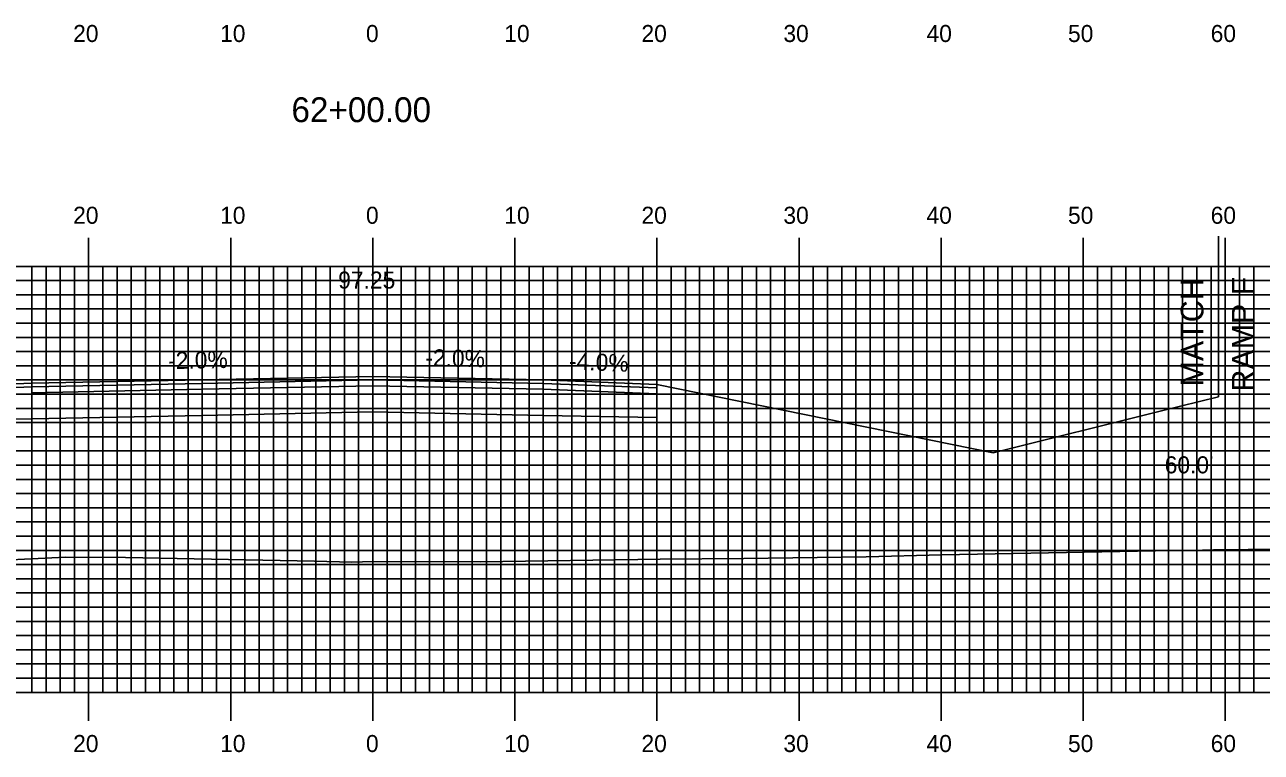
# Model space of a CAD drawing. Extents: x 1757856 to 1758199, y 442591 to 442811.
# Drawn here: x 1757997.1 to 1758084.2, y 442704.4 to 442755.7 of the extents above; entities that cross this region are included whole.
import ezdxf

# ---------------------------------------------------------------- set-up
doc = ezdxf.new("R2010")
doc.units = 0
for name, color, linetype in [('ANNOTATION', 7, 'Continuous'), ('D_Roadway_Centerline', 7, 'Continuous'), ('D_Roadway_Centerline_Text', 7, 'Continuous'), ('D_Roadway_Edge_Shoulder', 7, 'Continuous'), ('D_Roadway_Edge_TW', 7, 'Continuous'), ('D_Roadway_Pavement', 7, 'Continuous'), ('D_Roadway_SlopeLines', 7, 'Continuous'), ('D_Roadway_SubGrade', 7, 'Continuous'), ('D_Text_Standard', 7, 'Continuous'), ('H_V ANNOTATION', 7, 'Continuous'), ('MAJOR', 7, 'Continuous'), ('MINOR', 7, 'Continuous'), ('S_Roadway_Centerline', 7, 'Continuous')]:
    doc.layers.add(name, color=color, linetype=linetype)

msp = doc.modelspace()

# ---------------------------------------------------------------- linework, layer by layer
at = {"layer": 'D_Roadway_Centerline'}
msp.add_lwpolyline([(1758081.125, 442729.483), (1758081.127, 442729.483), (1758081.136, 442729.485)], dxfattribs=at)
at = {"layer": 'D_Roadway_Edge_Shoulder'}
for points in [[(1757997.622, 442730.436), (1757989.622, 442730.116), (1757989.622, 442729.866), (1757997.622, 442730.186)], [(1758033.622, 442730.676), (1758041.622, 442730.356), (1758041.622, 442730.106), (1758033.622, 442730.426)]]:
    msp.add_lwpolyline(points, close=True, dxfattribs=at)
at = {"layer": 'D_Roadway_Edge_TW'}
for points in [[(1758009.622, 442730.426), (1758009.622, 442730.676), (1758021.622, 442730.916), (1758033.622, 442730.676), (1758033.622, 442730.426), (1758021.622, 442730.666)], [(1758009.622, 442730.676), (1757997.622, 442730.436), (1757997.622, 442730.186), (1758009.622, 442730.426)]]:
    msp.add_lwpolyline(points, close=True, dxfattribs=at)
msp.add_lwpolyline([(1758009.622, 442730.676), (1758009.622, 442730.426)], dxfattribs=at)
at = {"layer": 'D_Roadway_Pavement'}
for points in [[(1758009.622, 442730.426), (1757997.622, 442730.186), (1757997.622, 442729.769), (1758009.622, 442730.009)], [(1758009.622, 442730.009), (1758009.622, 442730.426), (1758021.622, 442730.666), (1758033.622, 442730.426), (1758033.622, 442730.009), (1758021.622, 442730.249)], [(1758033.622, 442730.426), (1758041.622, 442730.106), (1758041.622, 442729.689), (1758033.622, 442730.009)]]:
    msp.add_lwpolyline(points, close=True, dxfattribs=at)
for points in [[(1757997.622, 442730.186), (1757997.622, 442729.769)], [(1758009.622, 442730.426), (1758009.622, 442730.009)], [(1758009.622, 442730.426), (1758009.622, 442730.009)]]:
    msp.add_lwpolyline(points, dxfattribs=at)
at = {"layer": 'D_Roadway_SlopeLines'}
msp.add_lwpolyline([(1758041.622, 442730.356), (1758065.295, 442725.525)], dxfattribs=at)
at = {"layer": 'D_Roadway_SubGrade'}
for p, q in [((1758081.136, 442740.782), (1758081.136, 442729.485)), ((1758081.136, 442729.485), (1758081.136, 442732.055)), ((1758081.136, 442729.485), (1758077.136, 442728.485)), ((1758077.136, 442728.485), (1758065.295, 442725.525))]:
    msp.add_line(p, q, dxfattribs=at)
for points in [[(1757997.622, 442729.769), (1757997.622, 442730.186), (1757989.622, 442729.866), (1757989.622, 442730.116), (1757979.448, 442727.572), (1757997.622, 442727.936)], [(1758009.622, 442730.009), (1757997.622, 442729.769), (1757997.622, 442727.936), (1758009.622, 442728.176)], [(1758009.622, 442728.176), (1758009.622, 442730.009), (1758021.622, 442730.249), (1758033.622, 442730.009), (1758033.622, 442728.176), (1758021.622, 442728.416)], [(1758033.622, 442730.009), (1758041.622, 442729.689), (1758041.622, 442730.106), (1758041.622, 442730.356), (1758041.622, 442728.016), (1758033.622, 442728.176)]]:
    msp.add_lwpolyline(points, close=True, dxfattribs=at)
msp.add_lwpolyline([(1758009.622, 442730.009), (1758009.622, 442728.176)], dxfattribs=at)
at = {"layer": 'MAJOR'}
for p, q in [((1758001.622, 442740.669), (1758001.622, 442738.665)), ((1758011.622, 442740.669), (1758011.622, 442738.665)), ((1758021.622, 442740.669), (1758021.622, 442738.665)), ((1758031.622, 442740.669), (1758031.622, 442738.665)), ((1758041.622, 442740.669), (1758041.622, 442738.665)), ((1758051.622, 442740.669), (1758051.622, 442738.665)), ((1758061.622, 442740.669), (1758061.622, 442738.665)), ((1758071.622, 442740.669), (1758071.622, 442738.665)), ((1758081.622, 442740.669), (1758081.622, 442738.665)), ((1757881.622, 442738.665), (1758161.622, 442738.665)), ((1757881.622, 442738.665), (1758161.622, 442738.665)), ((1758001.622, 442708.665), (1758001.622, 442738.665)), ((1758011.622, 442708.665), (1758011.622, 442738.665)), ((1758021.622, 442708.665), (1758021.622, 442738.665)), ((1758031.622, 442708.665), (1758031.622, 442738.665)), ((1758041.622, 442708.665), (1758041.622, 442738.665)), ((1758051.622, 442708.665), (1758051.622, 442738.665)), ((1758061.622, 442708.665), (1758061.622, 442738.665)), ((1758071.622, 442708.665), (1758071.622, 442738.665)), ((1758081.622, 442708.665), (1758081.622, 442738.665)), ((1757881.622, 442733.665), (1758161.622, 442733.665)), ((1757881.622, 442728.665), (1758161.622, 442728.665)), ((1757881.622, 442723.665), (1758161.622, 442723.665)), ((1757881.622, 442718.665), (1758161.622, 442718.665)), ((1757881.622, 442713.665), (1758161.622, 442713.665)), ((1757881.622, 442708.665), (1758161.622, 442708.665)), ((1757881.622, 442708.665), (1758161.622, 442708.665)), ((1758001.622, 442706.661), (1758001.622, 442708.665)), ((1758011.622, 442706.661), (1758011.622, 442708.665)), ((1758021.622, 442706.661), (1758021.622, 442708.665)), ((1758031.622, 442706.661), (1758031.622, 442708.665)), ((1758041.622, 442706.661), (1758041.622, 442708.665)), ((1758051.622, 442706.661), (1758051.622, 442708.665)), ((1758061.622, 442706.661), (1758061.622, 442708.665)), ((1758071.622, 442706.661), (1758071.622, 442708.665)), ((1758081.622, 442706.661), (1758081.622, 442708.665))]:
    msp.add_line(p, q, dxfattribs=at)
at = {"layer": 'MINOR'}
for p, q in [((1757997.622, 442708.665), (1757997.622, 442738.665)), ((1757998.622, 442708.665), (1757998.622, 442738.665)), ((1757999.622, 442708.665), (1757999.622, 442738.665)), ((1758000.622, 442708.665), (1758000.622, 442738.665)), ((1758002.622, 442708.665), (1758002.622, 442738.665)), ((1758003.622, 442708.665), (1758003.622, 442738.665)), ((1758004.622, 442708.665), (1758004.622, 442738.665)), ((1758005.622, 442708.665), (1758005.622, 442738.665)), ((1758006.622, 442708.665), (1758006.622, 442738.665)), ((1758007.622, 442708.665), (1758007.622, 442738.665)), ((1758008.622, 442708.665), (1758008.622, 442738.665)), ((1758009.622, 442708.665), (1758009.622, 442738.665)), ((1758010.622, 442708.665), (1758010.622, 442738.665)), ((1758012.622, 442708.665), (1758012.622, 442738.665)), ((1758013.622, 442708.665), (1758013.622, 442738.665)), ((1758014.622, 442708.665), (1758014.622, 442738.665)), ((1758015.622, 442708.665), (1758015.622, 442738.665)), ((1758016.622, 442708.665), (1758016.622, 442738.665)), ((1758017.622, 442708.665), (1758017.622, 442738.665)), ((1758018.622, 442708.665), (1758018.622, 442738.665)), ((1758019.622, 442708.665), (1758019.622, 442738.665)), ((1758020.622, 442708.665), (1758020.622, 442738.665)), ((1758022.622, 442708.665), (1758022.622, 442738.665)), ((1758023.622, 442708.665), (1758023.622, 442738.665)), ((1758024.622, 442708.665), (1758024.622, 442738.665)), ((1758025.622, 442708.665), (1758025.622, 442738.665)), ((1758026.622, 442708.665), (1758026.622, 442738.665)), ((1758027.622, 442708.665), (1758027.622, 442738.665)), ((1758028.622, 442708.665), (1758028.622, 442738.665)), ((1758029.622, 442708.665), (1758029.622, 442738.665)), ((1758030.622, 442708.665), (1758030.622, 442738.665)), ((1758032.622, 442708.665), (1758032.622, 442738.665)), ((1758033.622, 442708.665), (1758033.622, 442738.665)), ((1758034.622, 442708.665), (1758034.622, 442738.665)), ((1758035.622, 442708.665), (1758035.622, 442738.665)), ((1758036.622, 442708.665), (1758036.622, 442738.665)), ((1758037.622, 442708.665), (1758037.622, 442738.665)), ((1758038.622, 442708.665), (1758038.622, 442738.665)), ((1758039.622, 442708.665), (1758039.622, 442738.665)), ((1758040.622, 442708.665), (1758040.622, 442738.665)), ((1758042.622, 442708.665), (1758042.622, 442738.665)), ((1758043.622, 442708.665), (1758043.622, 442738.665)), ((1758044.622, 442708.665), (1758044.622, 442738.665)), ((1758045.622, 442708.665), (1758045.622, 442738.665)), ((1758046.622, 442708.665), (1758046.622, 442738.665)), ((1758047.622, 442708.665), (1758047.622, 442738.665)), ((1758048.622, 442708.665), (1758048.622, 442738.665)), ((1758049.622, 442708.665), (1758049.622, 442738.665)), ((1758050.622, 442708.665), (1758050.622, 442738.665)), ((1758052.622, 442708.665), (1758052.622, 442738.665)), ((1758053.622, 442708.665), (1758053.622, 442738.665)), ((1758054.622, 442708.665), (1758054.622, 442738.665)), ((1758055.622, 442708.665), (1758055.622, 442738.665)), ((1758056.622, 442708.665), (1758056.622, 442738.665)), ((1758057.622, 442708.665), (1758057.622, 442738.665)), ((1758058.622, 442708.665), (1758058.622, 442738.665)), ((1758059.622, 442708.665), (1758059.622, 442738.665)), ((1758060.622, 442708.665), (1758060.622, 442738.665)), ((1758062.622, 442708.665), (1758062.622, 442738.665)), ((1758063.622, 442708.665), (1758063.622, 442738.665)), ((1758064.622, 442708.665), (1758064.622, 442738.665)), ((1758065.622, 442708.665), (1758065.622, 442738.665)), ((1758066.622, 442708.665), (1758066.622, 442738.665)), ((1758067.622, 442708.665), (1758067.622, 442738.665)), ((1758068.622, 442708.665), (1758068.622, 442738.665)), ((1758069.622, 442708.665), (1758069.622, 442738.665)), ((1758070.622, 442708.665), (1758070.622, 442738.665)), ((1758072.622, 442708.665), (1758072.622, 442738.665)), ((1758073.622, 442708.665), (1758073.622, 442738.665)), ((1758074.622, 442708.665), (1758074.622, 442738.665)), ((1758075.622, 442708.665), (1758075.622, 442738.665)), ((1758076.622, 442708.665), (1758076.622, 442738.665)), ((1758077.622, 442708.665), (1758077.622, 442738.665)), ((1758078.622, 442708.665), (1758078.622, 442738.665)), ((1758079.622, 442708.665), (1758079.622, 442738.665)), ((1758080.622, 442708.665), (1758080.622, 442738.665)), ((1758082.622, 442708.665), (1758082.622, 442738.665)), ((1758083.622, 442708.665), (1758083.622, 442738.665)), ((1757881.622, 442737.665), (1758161.622, 442737.665)), ((1757881.622, 442736.665), (1758161.622, 442736.665)), ((1757881.622, 442735.665), (1758161.622, 442735.665)), ((1757881.622, 442734.665), (1758161.622, 442734.665)), ((1757881.622, 442732.665), (1758161.622, 442732.665)), ((1757881.622, 442731.665), (1758161.622, 442731.665)), ((1757881.622, 442730.665), (1758161.622, 442730.665)), ((1757881.622, 442729.665), (1758161.622, 442729.665)), ((1757881.622, 442727.665), (1758161.622, 442727.665)), ((1757881.622, 442726.665), (1758161.622, 442726.665)), ((1757881.622, 442725.665), (1758161.622, 442725.665)), ((1757881.622, 442724.665), (1758161.622, 442724.665)), ((1757881.622, 442722.665), (1758161.622, 442722.665)), ((1757881.622, 442721.665), (1758161.622, 442721.665)), ((1757881.622, 442720.665), (1758161.622, 442720.665)), ((1757881.622, 442719.665), (1758161.622, 442719.665)), ((1757881.622, 442717.665), (1758161.622, 442717.665)), ((1757881.622, 442716.665), (1758161.622, 442716.665)), ((1757881.622, 442715.665), (1758161.622, 442715.665)), ((1757881.622, 442714.665), (1758161.622, 442714.665)), ((1757881.622, 442712.665), (1758161.622, 442712.665)), ((1757881.622, 442711.665), (1758161.622, 442711.665)), ((1757881.622, 442710.665), (1758161.622, 442710.665)), ((1757881.622, 442709.665), (1758161.622, 442709.665))]:
    msp.add_line(p, q, dxfattribs=at)
at = {"layer": 'S_Roadway_Centerline'}
msp.add_lwpolyline([(1757938.966, 442717.046), (1757947.497, 442716.919), (1757951.509, 442717.005), (1757965.228, 442717.399), (1757972.726, 442717.596), (1757984.329, 442717.521), (1757986.504, 442717.521), (1757999.995, 442718.195), (1758004.218, 442718.161), (1758017.529, 442717.914), (1758020.15, 442717.828), (1758021.643, 442717.878), (1758029.205, 442717.867), (1758041.848, 442718.043), (1758047.726, 442718.088), (1758056.337, 442718.223), (1758061.682, 442718.344), (1758077.96, 442718.661), (1758080.017, 442718.691), (1758080.792, 442718.702), (1758100.242, 442718.897)], dxfattribs=at)

# ---------------------------------------------------------------- texts
at = {"layer": 'ANNOTATION'}
for s, height, rotation, p in [('RAMP F', 1.6, 90, (1758083.689, 442729.853)), ('MATCH', 1.6, 90, (1758080.089, 442730.214)), ('-2.0%', 1.2, 1.14576, (1758007.228, 442731.428)), ('-2.0%', 1.2, 358.85424, (1758025.308, 442731.643)), ('-4.0%', 1.2, 357.70939, (1758035.414, 442731.406))]:
    msp.add_text(s, height=height, rotation=rotation, dxfattribs=at).set_placement(p)
at = {"layer": 'D_Roadway_Centerline'}
for s, p in [('C', (1758021.617, 442730.916)), ('L', (1758021.622, 442730.909))]:
    msp.add_text(s, height=0.0146, dxfattribs=at).set_placement(p)
at = {"layer": 'D_Roadway_Centerline_Text'}
msp.add_text('97.25', height=1.2, dxfattribs=at).set_placement((1758019.187, 442737.102))
at = {"layer": 'D_Text_Standard'}
msp.add_text("60.0'", height=1.2, dxfattribs=at).set_placement((1758077.358, 442724.09))
at = {"layer": 'H_V ANNOTATION'}
for s, height, p in [('20', 1.2, (1758000.53, 442754.465)), ('10', 1.2, (1758010.873, 442754.465)), ('0', 1.2, (1758021.14, 442754.465)), ('10', 1.2, (1758030.873, 442754.465)), ('20', 1.2, (1758040.53, 442754.465)), ('30', 1.2, (1758050.52, 442754.465)), ('40', 1.2, (1758060.594, 442754.465)), ('50', 1.2, (1758070.552, 442754.465)), ('60', 1.2, (1758080.594, 442754.465)), ('62+00.00', 1.75, (1758015.895, 442748.821)), ('20', 1.2, (1758000.53, 442741.665)), ('10', 1.2, (1758010.873, 442741.665)), ('0', 1.2, (1758021.14, 442741.665)), ('10', 1.2, (1758030.873, 442741.665)), ('20', 1.2, (1758040.53, 442741.665)), ('30', 1.2, (1758050.52, 442741.665)), ('40', 1.2, (1758060.594, 442741.665)), ('50', 1.2, (1758070.552, 442741.665)), ('60', 1.2, (1758080.594, 442741.665)), ('20', 1.2, (1758000.53, 442704.465)), ('10', 1.2, (1758010.873, 442704.465)), ('0', 1.2, (1758021.14, 442704.465)), ('10', 1.2, (1758030.873, 442704.465)), ('20', 1.2, (1758040.53, 442704.465)), ('30', 1.2, (1758050.52, 442704.465)), ('40', 1.2, (1758060.594, 442704.465)), ('50', 1.2, (1758070.552, 442704.465)), ('60', 1.2, (1758080.594, 442704.465))]:
    msp.add_text(s, height=height, dxfattribs=at).set_placement(p)

doc.saveas('drawing.dxf')
